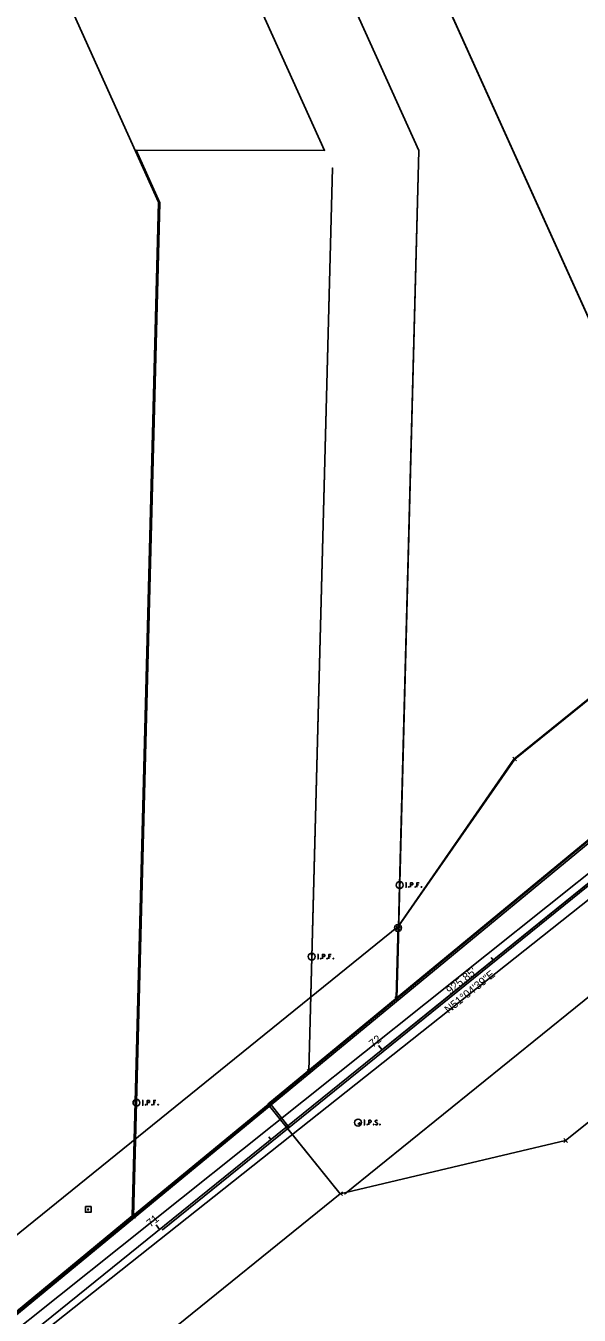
# Model space of a CAD drawing. Extents: x 2180160 to 2188891, y 366108 to 373879.
# Drawn here: x 2184867.3 to 2185060.8, y 370077.2 to 370528.3 of the extents above; entities that cross this region are included whole.
import ezdxf

# ---------------------------------------------------------------- set-up
doc = ezdxf.new("R2010")
doc.units = 0
for name, color, linetype in [('BD_X_Building', 7, 'Continuous'), ('GE_P_Alignment', 7, 'Continuous'), ('PV_X_Driveway', 7, 'Continuous'), ('RD_X_Concrete_Pad', 7, 'Continuous'), ('RD_X_RR_Cells', 7, 'Continuous'), ('RW_P_Easement_Area', 7, 'Continuous'), ('RW_P_Taking_Area', 7, 'Continuous'), ('RW_X_CL', 7, 'Continuous'), ('SC_Scratch1', 7, 'Continuous'), ('SC_Scratch11', 7, 'Continuous'), ('SC_Scratch3', 7, 'Continuous'), ('SC_Scratch4', 7, 'Continuous'), ('SC_Scratch5', 7, 'Continuous'), ('SC_Scratch6', 7, 'Continuous'), ('SC_Scratch8', 7, 'Continuous'), ('SV_P_Control_Cells_Set', 7, 'Continuous'), ('SV_P_Mon_Cells_Set', 7, 'Continuous'), ('SV_X_Mon_Cells_Found', 7, 'Continuous'), ('SV_X_Random_Point', 7, 'Continuous'), ('SV_X_Shot_Marker', 7, 'Continuous'), ('SV_X_Void_Area', 7, 'Continuous')]:
    doc.layers.add(name, color=color, linetype=linetype)

msp = doc.modelspace()

# ---------------------------------------------------------------- linework, layer by layer
at = {"layer": 'GE_P_Alignment'}
msp.add_line((2184991.92, 370170.03), (2185380.91, 370484.16), dxfattribs=at)
at = {"layer": 'PV_X_Driveway'}
for p, q in [((2185030.81, 370201.44), (2185030.06, 370202.37)), ((2184991.92, 370170.03), (2184990.66, 370171.58)), ((2184953.02, 370138.61), (2184952.26, 370139.55)), ((2184914.12, 370107.2), (2184912.86, 370108.76))]:
    msp.add_line(p, q, dxfattribs=at)
at = {"layer": 'RD_X_Concrete_Pad'}
msp.add_line((2185380.91, 370484.16), (2185030.81, 370201.44), dxfattribs=at)
at = {"layer": 'RD_X_RR_Cells'}
for p, q in [((2184998.3, 370211.83), (2184996.6, 370213.53)), ((2184996.6, 370211.83), (2184998.3, 370213.53))]:
    msp.add_line(p, q, dxfattribs=at)
msp.add_circle((2184997.45, 370212.68), 1.2, dxfattribs=at)
at = {"layer": 'RW_P_Easement_Area'}
for p, q in [((2184931.61, 370719.54), (2185124.18, 370293.01)), ((2185004.74, 370484.66), (2184997.03, 370187.86)), ((2184974.56, 370478.57), (2184966.35, 370162.49)), ((2184914.22, 370466.4), (2184905.01, 370111.77)), ((2185124.18, 370293.01), (2184905.01, 370111.77)), ((2184905.01, 370111.77), (2184427.83, 369717.47))]:
    msp.add_line(p, q, dxfattribs=at)
at = {"layer": 'RW_P_Taking_Area'}
for p, q in [((2185038.3, 370271.75), (2185271.7, 370460.23)), ((2184997.69, 370213.25), (2185038.3, 370271.75)), ((2185056.09, 370138.3), (2185207.8, 370260.82)), ((2184641.76, 369925.82), (2184997.69, 370213.25)), ((2184977.31, 370119.67), (2185056.09, 370138.3)), ((2184679.45, 369879.14), (2184977.31, 370119.67)), ((2184977.3, 370119.66), (2184977.3, 370119.66))]:
    msp.add_line(p, q, dxfattribs=at)
at = {"layer": 'RW_X_CL'}
msp.add_line((2184660.61, 369902.48), (2185380.91, 370484.16), dxfattribs=at)
at = {"layer": 'SC_Scratch1'}
for points in [[(2185902.93, 370933.53), (2185124.18, 370293.01), (2184997.02, 370187.86), (2184966.35, 370162.49), (2184974.56, 370478.57), (2184967.38, 370202.28), (2184966.35, 370162.49), (2184905.01, 370111.77), (2184906.05, 370151.56), (2184914.22, 370466.4), (2184905.93, 370484.78), (2184971.8, 370484.7), (2184870.37, 370709.34), (2184908.99, 371117.35)], [(2184939.13, 371117.41), (2184900.99, 370714.45), (2185004.74, 370484.66), (2184998.06, 370227.65), (2184997.03, 370187.86), (2185124.18, 370293.01), (2185111.39, 370321.35), (2184931.61, 370719.54), (2184969.27, 371117.49)]]:
    msp.add_lwpolyline(points, dxfattribs=at)
at = {"layer": 'SC_Scratch11'}
msp.add_lwpolyline([(2184427.75, 369717.42), (2184953.09, 370150.77), (2184959.46, 370142.91), (2184915.13, 370107.07), (2185381.71, 370484.31)], dxfattribs=at)
at = {"layer": 'SC_Scratch3'}
msp.add_lwpolyline([(2184850.31, 370607.16), (2184913.79, 370466.57), (2184905.61, 370151.73), (2184904.58, 370111.94), (2184427.75, 369717.48), (2184426.8, 369755.17), (2184325.48, 369674.85), (2184226.22, 369641.62), (2184171.21, 369552.57), (2184145.5, 369532.19), (2184164.14, 369508.68), (2184182.77, 369485.17), (2184243.46, 369487.83), (2184324.18, 369597.26), (2184399.06, 369656.61), (2184398.29, 369692.54), (2184427.76, 369717.47)], dxfattribs=at)
at = {"layer": 'SC_Scratch4'}
msp.add_lwpolyline([(2185898.94, 371118.61), (2185901.45, 370932.63), (2186129.11, 371120.01), (2185370.99, 370496.01), (2185380.69, 370483.98), (2185399.53, 370460.63), (2185361.86, 370507.33), (2185271.47, 370460.11), (2185108.08, 370328.3), (2185037.98, 370271.74), (2184997.75, 370213.58), (2184997.03, 370187.86), (2184952.11, 370150.89), (2184977.3, 370119.66), (2184958.46, 370143.01), (2184952.11, 370150.89), (2184426.3, 369718.09)], dxfattribs=at)
at = {"layer": 'SC_Scratch5'}
for p, q in [((2185384.67, 370487.88), (2183283.09, 368809.4)), ((2185389.97, 370481.23), (2183283.09, 368809.4)), ((2185400.59, 370460.97), (2184978.73, 370119.53)), ((2185124.23, 370292.97), (2184427.64, 369717.31))]:
    msp.add_line(p, q, dxfattribs=at)
msp.add_lwpolyline([(2184997.58, 370213.75), (2184996.89, 370188.03), (2184952.01, 370151.01), (2185124.17, 370293.03), (2185108.18, 370328.56), (2185271.42, 370460.55), (2185361.76, 370507.87), (2185370.91, 370496.56)], dxfattribs=at)
at = {"layer": 'SC_Scratch6'}
msp.add_lwpolyline([(2185899.27, 371119.5), (2185901.98, 370933.52), (2186129.44, 371121.15), (2185371.99, 370496.33), (2185381.71, 370484.31), (2185400.57, 370460.98), (2185371.99, 370496.33), (2184953.09, 370150.77), (2184427.75, 369717.42), (2184953.09, 370150.77), (2184959.46, 370142.91), (2184915.13, 370107.07), (2185381.71, 370484.31)], dxfattribs=at)
at = {"layer": 'SC_Scratch8'}
msp.add_lwpolyline([(2185898.94, 371118.61), (2185901.45, 370932.63), (2186129.11, 371120.01), (2185370.99, 370496.01), (2185380.69, 370483.98), (2185399.53, 370460.63), (2185361.86, 370507.33), (2185271.47, 370460.11), (2185108.08, 370328.3), (2185037.98, 370271.74), (2184997.75, 370213.58), (2184997.03, 370187.86), (2184952.11, 370150.89), (2184977.3, 370119.66), (2184958.46, 370143.01), (2184952.11, 370150.89), (2184863.14, 370077.66)], dxfattribs=at)
at = {"layer": 'SV_P_Control_Cells_Set'}
for p, q in [((2184996.3, 370187.26), (2184997.75, 370188.46)), ((2184997.63, 370187.13), (2184996.42, 370188.59)), ((2184965.68, 370161.83), (2184967.02, 370163.16)), ((2184965.68, 370163.16), (2184967.02, 370161.83)), ((2184904.35, 370111.11), (2184905.68, 370112.44)), ((2184904.35, 370112.44), (2184905.68, 370111.11))]:
    msp.add_line(p, q, dxfattribs=at)
msp.add_lwpolyline([(2184888.17, 370115.17), (2184890.15, 370115.17), (2184890.15, 370113.19), (2184888.17, 370113.19), (2184888.17, 370115.17)], dxfattribs=at)
msp.add_circle((2184889.16, 370114.18), 0.2, dxfattribs=at)
at = {"layer": 'SV_P_Mon_Cells_Set'}
for points in [[(2184985.54, 370145.38), (2184985.89, 370145.38)], [(2184985.71, 370143.78), (2184985.71, 370145.38)], [(2184987.28, 370143.78), (2184987.28, 370145.38), (2184987.81, 370145.38), (2184987.86, 370145.37), (2184987.94, 370145.34), (2184987.97, 370145.32), (2184988, 370145.29), (2184988.05, 370145.23), (2184988.08, 370145.17), (2184988.1, 370145.07), (2184988.1, 370144.92), (2184988.09, 370144.87), (2184988.07, 370144.79), (2184988.03, 370144.7), (2184987.98, 370144.66), (2184987.95, 370144.64), (2184987.89, 370144.61), (2184987.81, 370144.6), (2184987.28, 370144.6)], [(2184990.29, 370145.27), (2184990.26, 370145.29), (2184990.23, 370145.32), (2184990.13, 370145.36), (2184990.01, 370145.38), (2184989.92, 370145.38), (2184989.89, 370145.38), (2184989.75, 370145.34), (2184989.63, 370145.27), (2184989.55, 370145.17), (2184989.53, 370145.07), (2184989.53, 370144.99), (2184989.55, 370144.89), (2184989.64, 370144.8), (2184990.24, 370144.42), (2184990.3, 370144.37), (2184990.32, 370144.32), (2184990.34, 370144.25), (2184990.34, 370144.17), (2184990.33, 370144.1), (2184990.32, 370144.05), (2184990.3, 370143.98), (2184990.28, 370143.93), (2184990.25, 370143.9), (2184990.22, 370143.86), (2184990.19, 370143.83), (2184990.14, 370143.81), (2184990.11, 370143.79), (2184990.01, 370143.78), (2184989.86, 370143.78), (2184989.76, 370143.81), (2184989.61, 370143.9), (2184989.53, 370143.97)], [(2184985.54, 370143.78), (2184985.89, 370143.78)], [(2184986.67, 370144), (2184986.73, 370144), (2184986.76, 370143.97), (2184986.79, 370143.92), (2184986.79, 370143.86), (2184986.76, 370143.81), (2184986.73, 370143.78), (2184986.67, 370143.78), (2184986.64, 370143.81), (2184986.61, 370143.86), (2184986.61, 370143.92), (2184986.64, 370143.97), (2184986.67, 370144)], [(2184988.92, 370144), (2184988.97, 370144), (2184989.01, 370143.97), (2184989.04, 370143.92), (2184989.04, 370143.86), (2184989.01, 370143.81), (2184988.97, 370143.78), (2184988.92, 370143.78), (2184988.89, 370143.81), (2184988.85, 370143.86), (2184988.85, 370143.92), (2184988.89, 370143.97), (2184988.92, 370144)], [(2184991.1, 370144), (2184991.16, 370144), (2184991.19, 370143.97), (2184991.22, 370143.92), (2184991.22, 370143.86), (2184991.19, 370143.81), (2184991.16, 370143.78), (2184991.1, 370143.78), (2184991.07, 370143.81), (2184991.04, 370143.86), (2184991.04, 370143.92), (2184991.07, 370143.97), (2184991.1, 370144)]]:
    msp.add_lwpolyline(points, dxfattribs=at)
msp.add_circle((2184983.52, 370144.58), 1.2, dxfattribs=at)
at = {"layer": 'SV_X_Mon_Cells_Found'}
for p, q in [((2184998.08, 370227.82), (2184998.08, 370226.94)), ((2184967.3, 370202.76), (2184967.3, 370201.87)), ((2184906.03, 370151.65), (2184906.03, 370150.77))]:
    msp.add_line(p, q, dxfattribs=at)
for points in [[(2185000.11, 370228.5), (2185000.47, 370228.5)], [(2185000.11, 370226.9), (2185000.47, 370226.9)], [(2185000.29, 370226.9), (2185000.29, 370228.5)], [(2185001.25, 370227.12), (2185001.3, 370227.12), (2185001.34, 370227.09), (2185001.37, 370227.04), (2185001.37, 370226.98), (2185001.34, 370226.93), (2185001.3, 370226.9), (2185001.25, 370226.9), (2185001.22, 370226.93), (2185001.18, 370226.98), (2185001.18, 370227.04), (2185001.22, 370227.09), (2185001.25, 370227.12)], [(2185001.85, 370226.9), (2185001.85, 370228.5), (2185002.38, 370228.5), (2185002.44, 370228.49), (2185002.52, 370228.46), (2185002.55, 370228.44), (2185002.58, 370228.41), (2185002.63, 370228.35), (2185002.66, 370228.29), (2185002.68, 370228.19), (2185002.68, 370228.04), (2185002.67, 370227.99), (2185002.65, 370227.91), (2185002.6, 370227.82), (2185002.56, 370227.78), (2185002.53, 370227.76), (2185002.47, 370227.73), (2185002.38, 370227.72), (2185001.85, 370227.72)], [(2185003.5, 370227.12), (2185003.55, 370227.12), (2185003.59, 370227.09), (2185003.62, 370227.04), (2185003.62, 370226.98), (2185003.59, 370226.93), (2185003.55, 370226.9), (2185003.5, 370226.9), (2185003.46, 370226.93), (2185003.43, 370226.98), (2185003.43, 370227.04), (2185003.46, 370227.09), (2185003.5, 370227.12)], [(2185004.86, 370228.5), (2185004.1, 370228.5), (2185004.1, 370226.9)], [(2185004.1, 370227.72), (2185004.64, 370227.72)], [(2185005.65, 370227.12), (2185005.7, 370227.12), (2185005.73, 370227.09), (2185005.77, 370227.04), (2185005.77, 370226.98), (2185005.73, 370226.93), (2185005.7, 370226.9), (2185005.65, 370226.9), (2185005.61, 370226.93), (2185005.58, 370226.98), (2185005.58, 370227.04), (2185005.61, 370227.09), (2185005.65, 370227.12)], [(2184969.33, 370203.44), (2184969.68, 370203.44)], [(2184969.51, 370201.84), (2184969.51, 370203.44)], [(2184971.07, 370201.84), (2184971.07, 370203.44), (2184971.6, 370203.44), (2184971.66, 370203.43), (2184971.73, 370203.4), (2184971.77, 370203.38), (2184971.8, 370203.35), (2184971.84, 370203.29), (2184971.88, 370203.23), (2184971.9, 370203.13), (2184971.9, 370202.97), (2184971.89, 370202.92), (2184971.86, 370202.85), (2184971.82, 370202.76), (2184971.78, 370202.72), (2184971.74, 370202.7), (2184971.69, 370202.67), (2184971.6, 370202.66), (2184971.07, 370202.66)], [(2184974.08, 370203.44), (2184973.32, 370203.44), (2184973.32, 370201.84)], [(2184969.33, 370201.84), (2184969.68, 370201.84)], [(2184970.46, 370202.06), (2184970.52, 370202.06), (2184970.55, 370202.03), (2184970.59, 370201.98), (2184970.59, 370201.92), (2184970.55, 370201.87), (2184970.52, 370201.84), (2184970.46, 370201.84), (2184970.43, 370201.87), (2184970.4, 370201.92), (2184970.4, 370201.98), (2184970.43, 370202.03), (2184970.46, 370202.06)], [(2184972.71, 370202.06), (2184972.77, 370202.06), (2184972.8, 370202.03), (2184972.83, 370201.98), (2184972.83, 370201.92), (2184972.8, 370201.87), (2184972.77, 370201.84), (2184972.71, 370201.84), (2184972.68, 370201.87), (2184972.65, 370201.92), (2184972.65, 370201.98), (2184972.68, 370202.03), (2184972.71, 370202.06)], [(2184973.32, 370202.66), (2184973.86, 370202.66)], [(2184974.86, 370202.06), (2184974.92, 370202.06), (2184974.95, 370202.03), (2184974.98, 370201.98), (2184974.98, 370201.92), (2184974.95, 370201.87), (2184974.92, 370201.84), (2184974.86, 370201.84), (2184974.83, 370201.87), (2184974.8, 370201.92), (2184974.8, 370201.98), (2184974.83, 370202.03), (2184974.86, 370202.06)], [(2184908.06, 370152.33), (2184908.42, 370152.33)], [(2184908.06, 370150.73), (2184908.42, 370150.73)], [(2184908.24, 370150.73), (2184908.24, 370152.33)], [(2184909.2, 370150.95), (2184909.25, 370150.95), (2184909.29, 370150.92), (2184909.32, 370150.87), (2184909.32, 370150.81), (2184909.29, 370150.76), (2184909.25, 370150.73), (2184909.2, 370150.73), (2184909.17, 370150.76), (2184909.13, 370150.81), (2184909.13, 370150.87), (2184909.17, 370150.92), (2184909.2, 370150.95)], [(2184909.81, 370150.73), (2184909.81, 370152.33), (2184910.33, 370152.33), (2184910.39, 370152.32), (2184910.47, 370152.3), (2184910.5, 370152.27), (2184910.53, 370152.25), (2184910.58, 370152.18), (2184910.61, 370152.12), (2184910.63, 370152.02), (2184910.63, 370151.87), (2184910.62, 370151.82), (2184910.6, 370151.74), (2184910.55, 370151.65), (2184910.51, 370151.62), (2184910.48, 370151.59), (2184910.42, 370151.57), (2184910.33, 370151.55), (2184909.81, 370151.55)], [(2184911.45, 370150.95), (2184911.5, 370150.95), (2184911.54, 370150.92), (2184911.57, 370150.87), (2184911.57, 370150.81), (2184911.54, 370150.76), (2184911.5, 370150.73), (2184911.45, 370150.73), (2184911.41, 370150.76), (2184911.38, 370150.81), (2184911.38, 370150.87), (2184911.41, 370150.92), (2184911.45, 370150.95)], [(2184912.81, 370152.33), (2184912.05, 370152.33), (2184912.05, 370150.73)], [(2184912.05, 370151.55), (2184912.59, 370151.55)], [(2184913.6, 370150.95), (2184913.65, 370150.95), (2184913.69, 370150.92), (2184913.72, 370150.87), (2184913.72, 370150.81), (2184913.69, 370150.76), (2184913.65, 370150.73), (2184913.6, 370150.73), (2184913.56, 370150.76), (2184913.53, 370150.81), (2184913.53, 370150.87), (2184913.56, 370150.92), (2184913.6, 370150.95)]]:
    msp.add_lwpolyline(points, dxfattribs=at)
for centre, radius in [((2184998.08, 370227.7), 1.2), ((2184998.08, 370228.35), 0.16), ((2184967.3, 370202.64), 1.2), ((2184967.3, 370203.29), 0.16), ((2184906.03, 370151.53), 1.2), ((2184906.03, 370152.19), 0.16)]:
    msp.add_circle(centre, radius, dxfattribs=at)
at = {"layer": 'SV_X_Random_Point'}
for p, q in [((2185037.63, 370271.09), (2185038.97, 370272.42)), ((2185037.63, 370272.42), (2185038.97, 370271.09)), ((2184997.02, 370212.58), (2184998.35, 370213.91)), ((2184997.02, 370213.91), (2184998.35, 370212.58)), ((2185055.43, 370137.64), (2185056.76, 370138.97)), ((2185055.43, 370138.97), (2185056.76, 370137.64)), ((2184976.68, 370119.03), (2184978.02, 370120.37)), ((2184976.68, 370120.37), (2184978.02, 370119.03))]:
    msp.add_line(p, q, dxfattribs=at)
at = {"layer": 'SV_X_Shot_Marker'}
for p, q in [((2184983.46, 370144.19), (2184984.46, 370144.19)), ((2184983.96, 370144.69), (2184983.96, 370143.69)), ((2184983.96, 370144.19), (2184983.96, 370144.19))]:
    msp.add_line(p, q, dxfattribs=at)

# ---------------------------------------------------------------- texts
at = {"layer": 'BD_X_Building'}
msp.add_text('N51°04\'39"E', height=2.8, rotation=38.9226, dxfattribs=at).set_placement((2185015.13, 370182.6))
at = {"layer": 'PV_X_Driveway'}
for s, p in [('72', (2184988.72, 370170.66)), ('71', (2184910.91, 370107.82))]:
    msp.add_text(s, height=2.8, rotation=38.9226, dxfattribs=at).set_placement(p)
at = {"layer": 'SV_X_Void_Area'}
msp.add_text("925.85'", height=2.8, rotation=38.9226, dxfattribs=at).set_placement((2185015.73, 370189.3))

doc.saveas('drawing.dxf')
